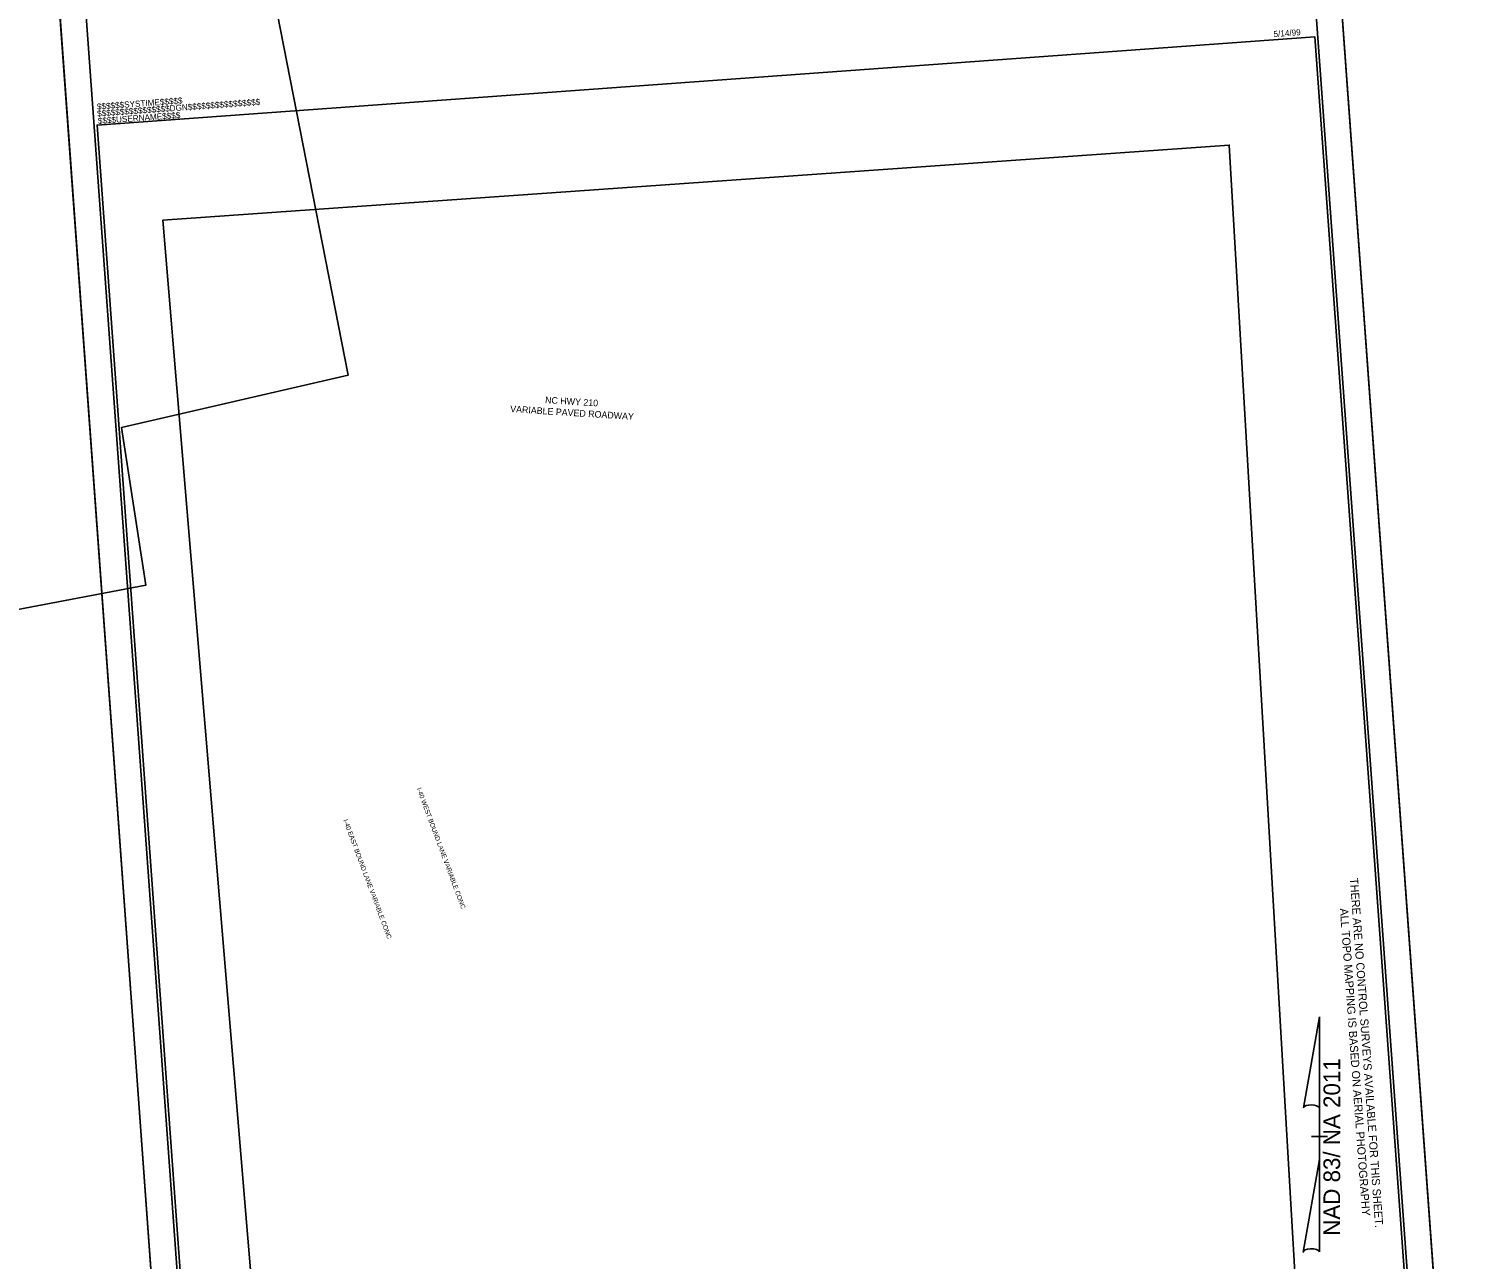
# Model space of a CAD drawing. Extents: x 2130580 to 2132747, y 641711 to 644338.
# Drawn here: x 2131506 to 2132747, y 642404 to 643462 of the extents above; entities that cross this region are included whole.
import ezdxf

# ---------------------------------------------------------------- set-up
doc = ezdxf.new("R2010")
doc.units = 0
for name, color, linetype in [('Prop Horizontal Alignment Direction Label', 7, 'Continuous'), ('Prop North Arrow NAD83 for Plan Sheets CELL', 7, 'Continuous'), ('Raster_Level_1', 7, 'Continuous'), ('Scratch_Level_1', 7, 'Continuous'), ('Sheet Border Standard 30in CELL', 7, 'Continuous'), ('Sheet Cutting Line CELL', 7, 'Continuous'), ('Sheet Plot Border Inside CELL', 7, 'Continuous'), ('Sheet Plot Border Outside CELL', 7, 'Continuous')]:
    doc.layers.add(name, color=color, linetype=linetype)

msp = doc.modelspace()

# ---------------------------------------------------------------- linework, layer by layer
at = {"layer": 'Prop North Arrow NAD83 for Plan Sheets CELL'}
for p, q in [((2132602.6, 642534), (2132616.4, 642612.3)), ((2132616.5, 642612.3), (2132616.4, 642612.3)), ((2132616.5, 642612.3), (2132616.4, 642612.3)), ((2132616.5, 642612.3), (2132616.5, 642531.5)), ((2132616.5, 642489.6), (2132616.5, 642533.9)), ((2132616.5, 642531.5), (2132616.5, 642533.8)), ((2132609.7, 642509.2), (2132609.6, 642509.2)), ((2132615.7, 642509.2), (2132609.7, 642509.2)), ((2132609.8, 642509.2), (2132623.3, 642509.2)), ((2132616.5, 642489.6), (2132602.3, 642409.8)), ((2132616.5, 642410.1), (2132616.5, 642489.6))]:
    msp.add_line(p, q, dxfattribs=at)
for centre, start_param, end_param in [((2132609.5, 642533.2), 0.216388, 2.908219), ((2132609.5, 642409.5), 0.201328, 3.141593)]:
    msp.add_ellipse(centre, major_axis=(7.15, -0.05), ratio=0.461098, start_param=start_param, end_param=end_param, dxfattribs=at)
at = {"layer": 'Raster_Level_1'}
msp.add_lwpolyline([(2132607.7, 642180.7), (2132538.9, 643362), (2131621.6, 643297.4), (2131731.3, 641985.8), (2132523.3, 642035.1), (2132514, 642175.6)], close=True, dxfattribs=at)
at = {"layer": 'Scratch_Level_1'}
msp.add_lwpolyline([(2131551.1, 644337.9), (2130579.8, 644180.7), (2130824.5, 642834.6), (2131607.1, 642983.6), (2131586, 643119), (2131781.2, 643164.2)], close=True, dxfattribs=at)
at = {"layer": 'Sheet Border Standard 30in CELL'}
msp.add_line((2132612.4, 643454.2), (2132612.4, 643454.2), dxfattribs=at)
msp.add_lwpolyline([(2132720.7, 641959.1), (2132612.4, 643455.2), (2131565.1, 643379.3), (2131673.5, 641883.2)], close=True, dxfattribs=at)
at = {"layer": 'Sheet Cutting Line CELL'}
for p, q in [((2132746.9, 641943.9), (2132625.2, 643623.5)), ((2131528.1, 643544.1), (2131649.8, 641864.5))]:
    msp.add_line(p, q, dxfattribs=at)
at = {"layer": 'Sheet Plot Border Inside CELL'}
msp.add_lwpolyline([(2132724.2, 641946.8), (2132603.8, 643608.9), (2131551.4, 643532.7), (2131671.8, 641870.6)], close=True, dxfattribs=at)
at = {"layer": 'Sheet Plot Border Outside CELL'}
msp.add_lwpolyline([(2132746.9, 641943.9), (2132625.2, 643623.5), (2131528.1, 643544.1), (2131649.8, 641864.5)], close=True, dxfattribs=at)

# ---------------------------------------------------------------- texts
at = {"layer": 'Prop Horizontal Alignment Direction Label'}
for s, height, rotation, p in [('NC HWY 210 ', 5.687, 356.3624, (2131950.3, 643140.1)), ('VARIABLE PAVED ROADWAY', 5.687, 356.3624, (2131920.3, 643132.4)), ('I-40 WEST BOUND LANE VARIABLE CONC', 4, 290.3892, (2131839.9, 642808.5)), ('I-40 EAST BOUND LANE VARIABLE CONC', 4, 290.3892, (2131776.8, 642781.3)), ('THERE ARE NO CONTROL SURVEYS AVAILABLE FOR THIS SHEET.', 7, 274.143, (2132642.6, 642731.4)), ('ALL TOPO MAPPING IS BASED ON AERIAL PHOTOGRAPHY', 7, 274.143, (2132634, 642705.3))]:
    msp.add_text(s, height=height, rotation=rotation, dxfattribs=at).set_placement(p)
at = {"layer": 'Prop North Arrow NAD83 for Plan Sheets CELL'}
msp.add_text('NAD 83/ NA 2011', height=14.365, rotation=89.9761, dxfattribs=at).set_placement((2132634.2, 642423.9))
at = {"layer": 'Sheet Border Standard 30in CELL'}
for s, p in [('5/14/99', (2132577.1, 643454.9)), ('$$$$$$SYSTIME$$$$$', (2131565.2, 643392.5)), ('$$$$$$$$$$$$$$$$DGN$$$$$$$$$$$$$$$$', (2131565.4, 643386.5)), ('$$$$USERNAME$$$$', (2131566, 643380.2))]:
    msp.add_text(s, height=5.25, rotation=4.143, dxfattribs=at).set_placement(p)

doc.saveas('drawing.dxf')
